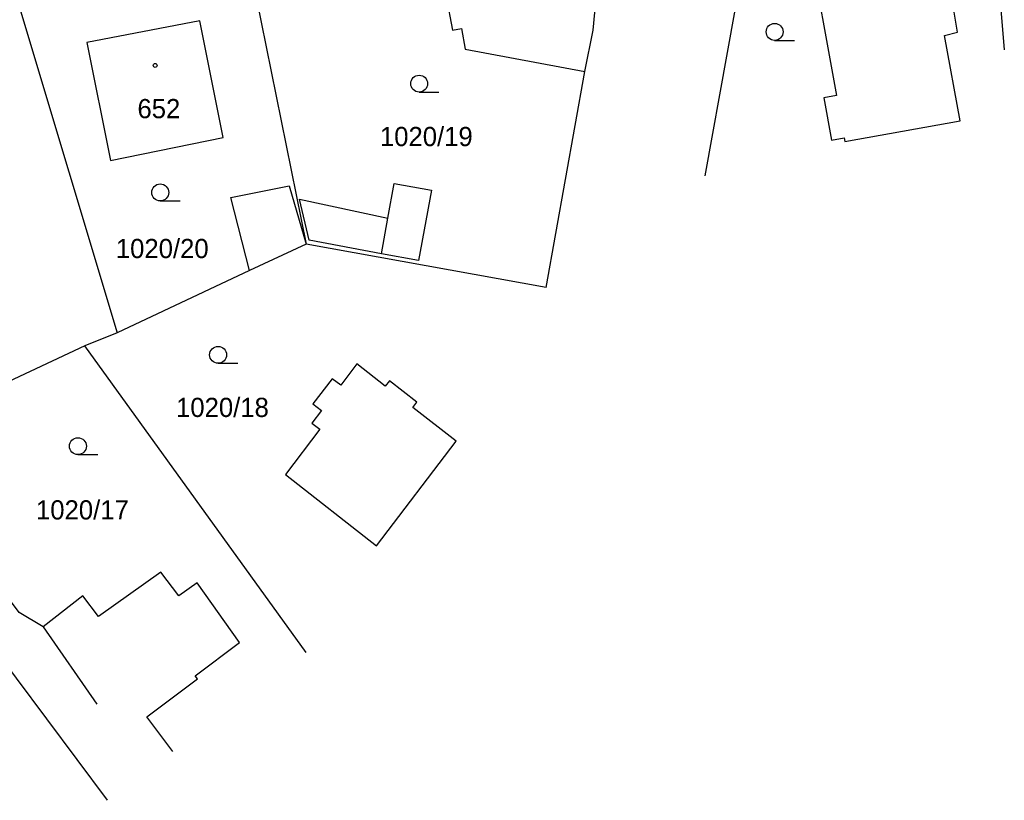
# Model space of a CAD drawing. Extents: x -793666 to -785424, y -1118958 to -1108761.
# Drawn here: x -792094.3 to -792007.1, y -1109985.6 to -1109916.5 of the extents above; entities that cross this region are included whole.
import ezdxf

# ---------------------------------------------------------------- set-up
doc = ezdxf.new("R2010")
doc.units = 0
for name, color, linetype in [('Hranice parcel', 7, 'Continuous'), ('Parcelní čísla', 7, 'Continuous'), ('Vnitřní kresba', 7, 'Continuous'), ('Značky budov', 7, 'Continuous'), ('Značky kultur', 7, 'Continuous')]:
    doc.layers.add(name, color=color, linetype=linetype)

msp = doc.modelspace()

# ---------------------------------------------------------------- linework, layer by layer
at = {"layer": 'Hranice parcel'}
for p, q in [((-792008.86, -1109898.91), (-792007.12, -1109919.15)), ((-792073.91, -1109911.8), (-792068.93, -1109936.34)), ((-792094.23, -1109915.7), (-792085.66, -1109944.17)), ((-792047.69, -1109940.18), (-792044.25, -1109921.05)), ((-792047.69, -1109940.18), (-792068.93, -1109936.34)), ((-792085.66, -1109944.17), (-792088.52, -1109945.34)), ((-792088.52, -1109945.34), (-792107.12, -1109954.06)), ((-792068.92, -1109972.46), (-792088.52, -1109945.34))]:
    msp.add_line(p, q, dxfattribs=at)
for points in [[(-792025.32, -1109902.4), (-792027.34, -1109904.01), (-792028.91, -1109905.95), (-792029.69, -1109908.43), (-792033.64, -1109930.28)], [(-792044.25, -1109921.05), (-792043.53, -1109917.41), (-792043.21, -1109914.24), (-792043.83, -1109911.81), (-792045.02, -1109910.01), (-792047.7, -1109908.05), (-792050.92, -1109907.37)], [(-792021.29, -1109926.93), (-792021.23, -1109927.25), (-792011.03, -1109925.41), (-792012.42, -1109917.86), (-792011.25, -1109917.57), (-792011.76, -1109914.54), (-792012.99, -1109914.77), (-792014.38, -1109907.21), (-792024.55, -1109909.04), (-792021.97, -1109923.19), (-792023.11, -1109923.4), (-792022.43, -1109927.14), (-792021.29, -1109926.93)], [(-792056.83, -1109908.43), (-792056.29, -1109911.33), (-792057.09, -1109911.48), (-792055.98, -1109917.41), (-792055.18, -1109917.26), (-792054.84, -1109919.07), (-792044.25, -1109921.05)], [(-792088.35, -1109918.48), (-792086.24, -1109928.92), (-792076.27, -1109926.91), (-792078.34, -1109916.58), (-792088.35, -1109918.48)], [(-792068.93, -1109936.34), (-792073.93, -1109938.68), (-792085.66, -1109944.17)], [(-792065.87, -1109948.82), (-792066.63, -1109948.24), (-792068.33, -1109950.48), (-792067.57, -1109951.06), (-792068.42, -1109952.18), (-792067.73, -1109952.7), (-792070.75, -1109956.73), (-792062.7, -1109963.04), (-792055.65, -1109953.76), (-792059.49, -1109950.78), (-792059.14, -1109950.32), (-792061.56, -1109948.44), (-792061.92, -1109948.9), (-792064.45, -1109946.93), (-792065.87, -1109948.82)], [(-792080.73, -1109981.22), (-792083.02, -1109978.17), (-792078.54, -1109974.81), (-792078.75, -1109974.53), (-792074.84, -1109971.6), (-792078.59, -1109966.31), (-792080.2, -1109967.46), (-792081.8, -1109965.36), (-792087.3, -1109969.29), (-792088.71, -1109967.47), (-792092.22, -1109970.19), (-792094.35, -1109968.93), (-792099.44, -1109962.12), (-792099.8, -1109962.39), (-792106, -1109953.95), (-792108.84, -1109955.74)], [(-792108.84, -1109955.74), (-792102.41, -1109964.34), (-792097.32, -1109971.15), (-792086.56, -1109985.55)]]:
    msp.add_lwpolyline(points, dxfattribs=at)
at = {"layer": 'Vnitřní kresba'}
for p, q in [((-792075.61, -1109932.21), (-792070.42, -1109931.16)), ((-792070.42, -1109931.16), (-792068.93, -1109936.34)), ((-792061.69, -1109934.04), (-792061.14, -1109930.98)), ((-792061.14, -1109930.98), (-792057.84, -1109931.57)), ((-792057.84, -1109931.57), (-792058.97, -1109937.79)), ((-792073.93, -1109938.68), (-792075.61, -1109932.21)), ((-792069.53, -1109932.35), (-792061.69, -1109934.04)), ((-792068.66, -1109935.98), (-792069.53, -1109932.35)), ((-792062.26, -1109937.19), (-792061.69, -1109934.04)), ((-792062.26, -1109937.19), (-792068.66, -1109935.98)), ((-792058.97, -1109937.79), (-792062.26, -1109937.19)), ((-792092.22, -1109970.19), (-792087.45, -1109977.03))]:
    msp.add_line(p, q, dxfattribs=at)
at = {"layer": 'Značky budov'}
msp.add_circle((-792082.297, -1109920.519), 0.175, dxfattribs=at)
at = {"layer": 'Značky kultur'}
for p, q in [((-792027.453, -1109918.3), (-792025.703, -1109918.3)), ((-792058.923, -1109922.88), (-792057.173, -1109922.88)), ((-792081.843, -1109932.51), (-792080.093, -1109932.51)), ((-792076.723, -1109946.88), (-792074.973, -1109946.88)), ((-792089.133, -1109954.96), (-792087.383, -1109954.96))]:
    msp.add_line(p, q, dxfattribs=at)
for centre in [(-792027.453, -1109917.55), (-792058.923, -1109922.13), (-792081.843, -1109931.76), (-792076.723, -1109946.13), (-792089.133, -1109954.21)]:
    msp.add_circle(centre, 0.75, dxfattribs=at)

# ---------------------------------------------------------------- texts
at = {"layer": 'Parcelní čísla'}
for s, p in [('652', (-792083.864, -1109925.19)), ('1020/19', (-792062.398, -1109927.66)), ('1020/20', (-792085.778, -1109937.57)), ('1020/18', (-792080.448, -1109951.63)), ('1020/17', (-792092.848, -1109960.7))]:
    msp.add_text(s, height=1.7, dxfattribs=at).set_placement(p)

doc.saveas('drawing.dxf')
